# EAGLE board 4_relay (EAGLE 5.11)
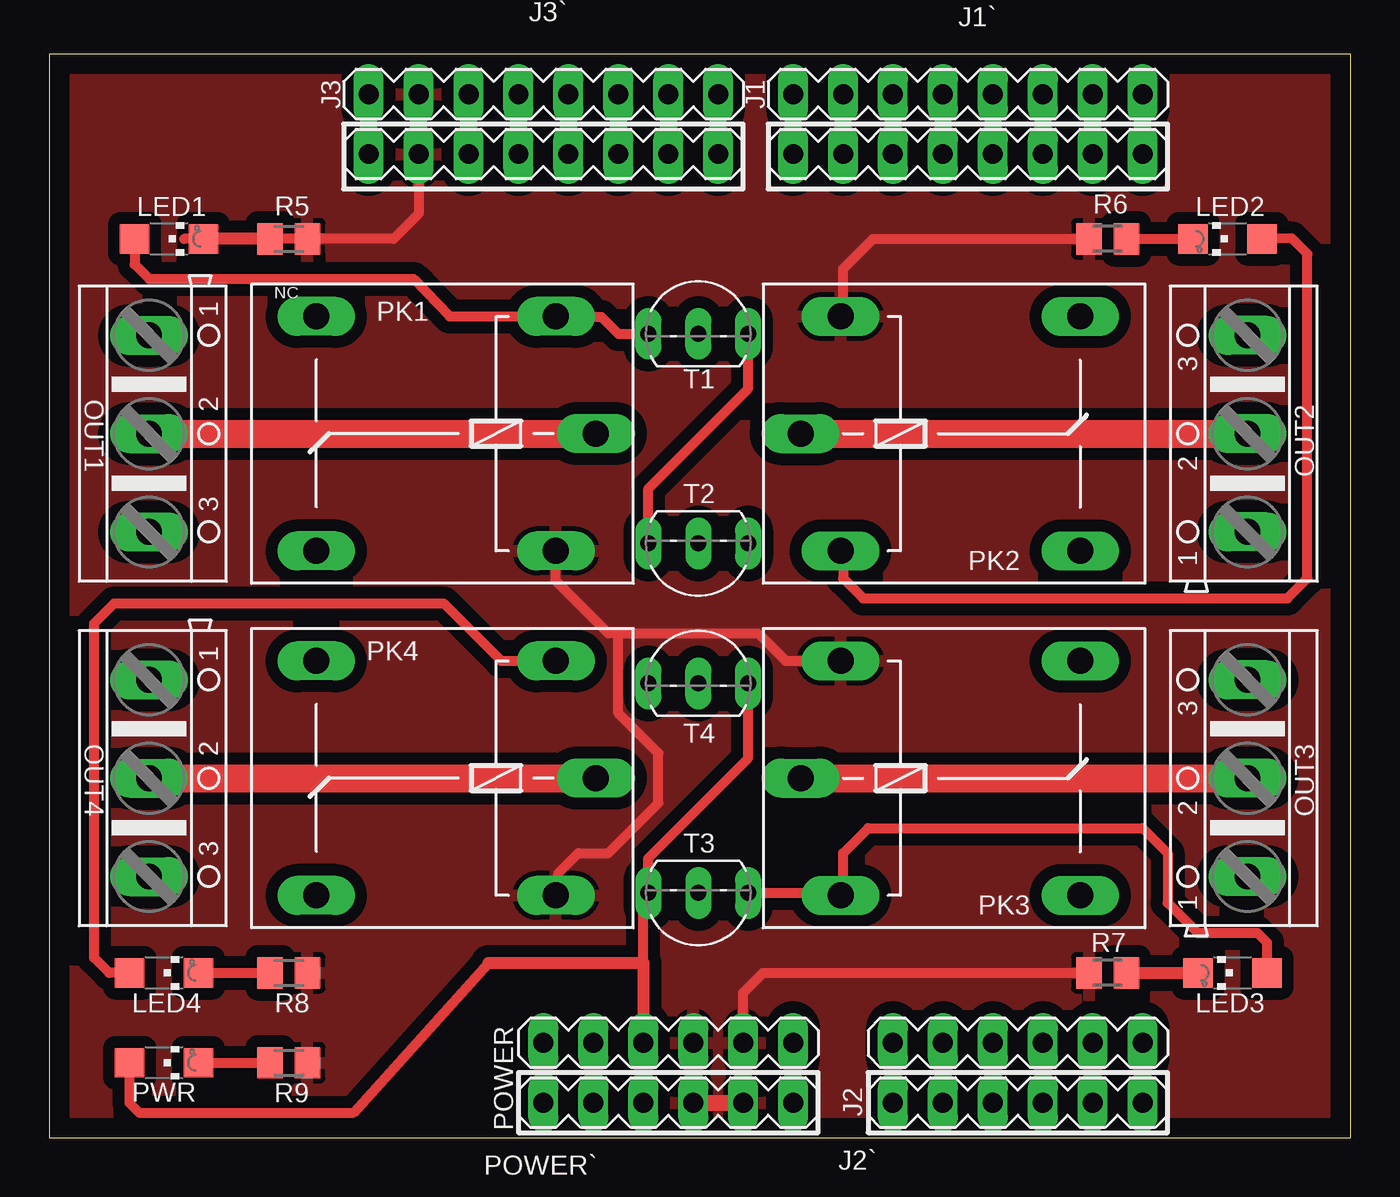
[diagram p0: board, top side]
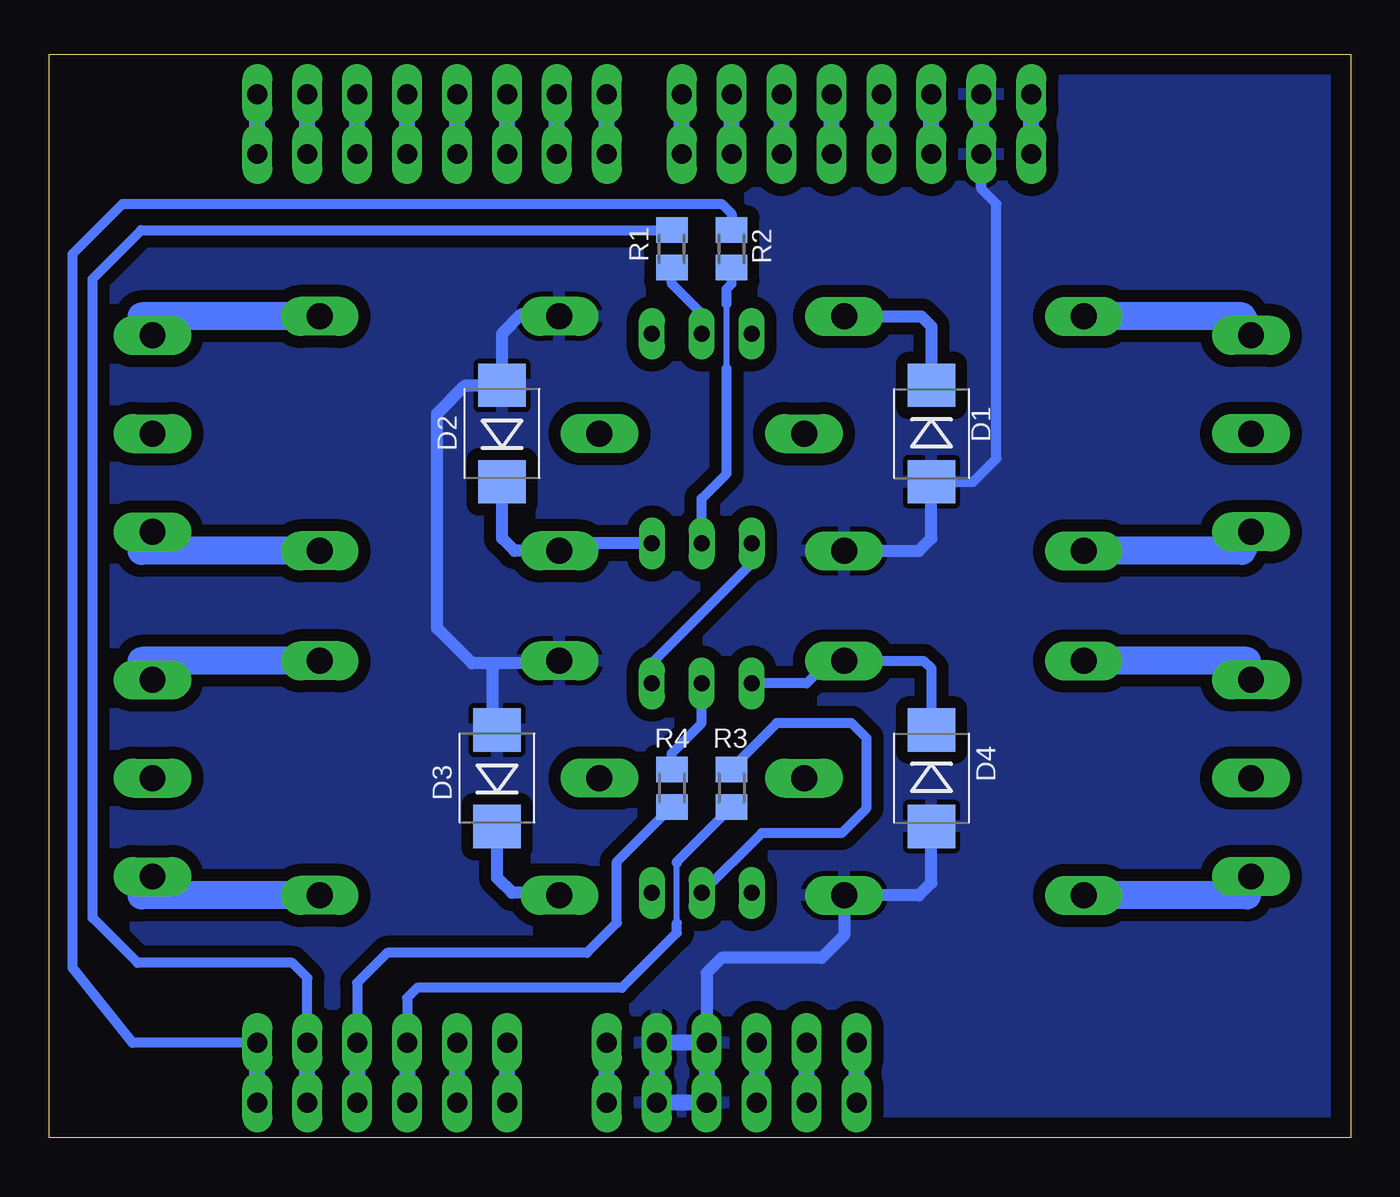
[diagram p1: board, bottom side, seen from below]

Size 66.22 x 55.11 mm. Coordinates in mm from the lower left corner, seen from the top.
Outline: 0,0 66.22,0 66.22,55.11 0,55.11 0,0
Copper layers (1*16): Top 0.035mm / dielectric 1.5mm / Bottom 0.035mm
Design rules "default": minimum track width 10mil, minimum drill 24mil, track to track 8mil, track to pad 8mil, pad to pad 8mil, via to via 8mil, smd to smd 8mil, copper to edge 40mil, drill to drill 8mil, minimum pad ring 10mil, minimum via ring 8mil, stop-mask expansion 4mil, vias tented up to drill 0mil, thermal gap 10mil

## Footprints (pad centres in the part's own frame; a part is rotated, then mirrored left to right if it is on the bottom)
DIODE-HV = smd 2.2 x 2.4: A 2.454,0; C -2.454,0
MA08-1 = drill 1.016 long: 1 -8.89,0; 2 -6.35,0; 3 -3.81,0; 4 -1.27,0; 5 1.27,0; 6 3.81,0; 7 6.35,0; 8 8.89,0
MA06-1 = drill 1.016 long: 1 -6.35,0; 2 -3.81,0; 3 -1.27,0; 4 1.27,0; 5 3.81,0; 6 6.35,0
CHIPLED_1206 = smd 1.5 x 1.5: A 0,-1.75; C 0,1.75
AK500/3 = drill 1.321 long: 1 -5.004,0; 2 0,0; 3 5.004,0
G5LE = drill 1.321 long: 1 -7.493,-5.969; 2 -7.493,5.969; O 4.699,5.969; P -9.525,0; S 4.699,-5.969
M0805 = smd 1.3 x 1.6: 1 -0.95,0; 2 0.95,0
TO92-EBC = drill 0.813 long: B 0,-1.27; C -2.54,-1.27; E 2.54,-1.27

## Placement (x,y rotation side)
D1  [DIODE-HV]  21.34,35.81 270 bottom
D2  [DIODE-HV]  43.18,35.81 90 bottom
D3  [DIODE-HV]  43.43,18.29 90 bottom
D4  [DIODE-HV]  21.34,18.29 270 bottom
J1  [MA08-1]  46.74,53.09 0 top
J1`  [MA08-1]  46.74,50.04 0 top
J2  [MA06-1]  49.28,4.83 0 top
J2`  [MA06-1]  49.28,1.78 0 top
J3  [MA08-1]  25.15,53.09 0 top
J3`  [MA08-1]  25.15,50.04 0 top
LED1  [CHIPLED_1206]  6.1,45.72 270 top
LED2  [CHIPLED_1206]  59.94,45.72 90 top
LED3  [CHIPLED_1206]  60.2,8.38 90 top
LED4  [CHIPLED_1206]  5.84,8.38 270 top
OUT1  [AK500/3]  5.08,35.81 270 top
OUT2  [AK500/3]  60.96,35.81 90 top
OUT3  [AK500/3]  60.96,18.29 90 top
OUT4  [AK500/3]  5.08,18.29 270 top
PK1  G5LE  [G5LE]  18.29,35.81 180 top
PK2  G5LE  [G5LE]  47.75,35.81 0 top
PK3  G5LE  [G5LE]  47.75,18.29 0 top
PK4  G5LE  [G5LE]  18.29,18.29 180 top
POWER  [MA06-1]  31.5,4.83 0 top
POWER`  [MA06-1]  31.5,1.78 0 top
PWR  [CHIPLED_1206]  5.84,3.81 270 top
R1  [M0805]  34.54,45.21 270 bottom
R2  [M0805]  31.5,45.21 270 bottom
R3  [M0805]  31.5,17.78 90 bottom
R4  [M0805]  34.54,17.78 90 bottom
R5  [M0805]  12.19,45.72 180 top
R6  [M0805]  53.85,45.72 0 top
R7  [M0805]  53.85,8.38 0 top
R8  [M0805]  12.19,8.38 180 top
R9  [M0805]  12.19,3.81 180 top
T1  BC558B  [TO92-EBC]  33.02,42.16 0 top
T2  BC558B  [TO92-EBC]  33.02,28.96 180 top
T3  BC558B  [TO92-EBC]  33.02,11.18 180 top
T4  BC558B  [TO92-EBC]  33.02,24.38 0 top

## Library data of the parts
D1-D4 = moja
J1 J1` J2 J2` J3 J3` POWER POWER` = con-lstb_v2; OC_FARNELL: unknown; OC_NEWARK: unknown
LED1-LED4 PWR = led
OUT1-OUT4 = con-ptr500; OC_FARNELL: unknown; OC_NEWARK: unknown
PK1-PK4 = relay2; OC_FARNELL: unknown; OC_NEWARK: unknown
R1-R9 = rcl
T1-T4 = transistor-pnp

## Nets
GND: D1.A D2.A D3.A D4.A J3.2 J3`.2 PK1.2 PK2.2 PK3.2 PK4.2 POWER.4 POWER.5 POWER`.4 POWER`.5 R5.1 R6.1 R7.1 R8.1 R9.1
N$1: OUT1.2 PK1.P
N$2: OUT1.3 PK1.O
N$3: OUT1.1 PK1.S
N$4: R1.2 T1.B
N$5: LED1.C R5.2
N$6: D1.C LED1.A PK1.1 T1.C
N$7: OUT3.2 PK3.P
N$8: POWER.1 POWER`.1
N$9: POWER.2 POWER`.2
N$10: OUT2.2 PK2.P
N$11: OUT2.3 PK2.O
N$12: OUT2.1 PK2.S
N$13: LED2.C R6.2
N$14: D2.C LED2.A PK2.1 T2.C
N$15: OUT3.3 PK3.O
N$16: R2.2 T2.B
N$17: POWER.6 POWER`.6
N$18: OUT3.1 PK3.S
N$19: LED3.C R7.2
N$20: D3.C LED3.A PK3.1 T3.C
N$21: R3.2 T3.B
N$22: J3.1 J3`.1
N$23: OUT4.2 PK4.P
N$24: OUT4.3 PK4.O
N$25: OUT4.1 PK4.S
N$26: LED4.C R8.2
N$27: D4.C LED4.A PK4.1 T4.C
N$28: R4.2 T4.B
N$29: PWR.C R9.2
N$30: J3.7 J3`.7
N$31: J3.8 J3`.8
N$32: J2.1 J2`.1
N$33: J2.2 J2`.2
N$38: J1.1 J1`.1
N$39: J1.2 J1`.2
N$40: J1.3 J1`.3
N$41: J1.4 J1`.4
N$42: J1.5 J1`.5
N$43: J1.6 J1`.6
N$44: J1.7 J1`.7
N$45: J1.8 J1`.8
PB2: J3.6 J3`.6
PB3: J3.5 J3`.5
PB4: J3.4 J3`.4
PB5: J3.3 J3`.3
PC2: J2.3 J2`.3 R3.1
PC3: J2.4 J2`.4 R4.1
PC4: J2.5 J2`.5 R1.1
PC5: J2.6 J2`.6 R2.1
VCC: POWER.3 POWER`.3 PWR.A T1.E T2.E T3.E T4.E

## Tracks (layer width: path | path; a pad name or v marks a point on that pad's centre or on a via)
GND
  Top 0.254: PK1.2 25.65,29.46
  Top 0.508: R7.1 36.32,8.38 35.31,7.37 POWER.5 | 6.86,45.72 R5.1 17.53,45.72 18.8,46.99 J3`.2 | R6.1 41.91,45.72 40.39,44.2 40.39,41.91 | PK3.2 37.47,24.26 36.07,25.65 28.96,25.65 | PK1.2 25.78,28.32 28.45,25.65 28.96,25.65 | 28.96,25.65 28.96,21.59 30.99,19.56 30.99,17.02 28.45,14.48 26.92,14.48 25.91,13.46 25.91,12.45
  Top 0.61: PK2.2 40.39,41.91 | PK1.2 25.65,29.97 | 25.65,12.45 PK4.2 25.91,12.45
  Top 0.813: POWER.4 POWER`.4 POWER`.5 POWER.5 | J3`.2 J3.2
  Bottom 0.254: 22.1,12.45 23.37,12.45 PK4.2 | 43.69,21.34 D3.A | PK3.2 41.15,23.88
  Bottom 0.508: D1.A 19.22,33.36 18.03,34.54 18.03,47.5 18.8,48.26 J3`.2
  Bottom 0.61: PK2.2 40.39,41.91 42.16,41.91 43.18,40.89 D2.A 45.04,38.27 46.48,36.83 46.48,25.91 44.7,24.13 43.43,24.13 | 43.43,24.13 40.39,24.13 PK3.2 | 43.69,21.34 43.69,23.88 43.43,24.13 | D1.A 21.34,30.48 21.97,29.85 PK1.2 | D4.A 21.34,12.95 21.97,12.32 PK4.2 25.78,10.29 26.92,9.14 32,9.14 32.77,8.38 POWER.4
  Bottom 0.813: J3`.2 J3.2 | POWER.4 POWER`.4 POWER`.5 POWER.5 POWER.4
  pour Bottom (isolate 0.61): -1.52,56.64 67.82,56.9 67.82,-1.27 -1.52,-1.52
  pour Top (isolate 0.61): -1.27,56.39 67.06,56.13 67.06,-0.76 -1.27,-0.51
N$1
  Top 1.422: OUT1.2 PK1.P
N$2
  Bottom 1.422: PK1.O 5.54,29.85 OUT1.3
N$3
  Bottom 1.422: PK1.S 5.54,41.78 OUT1.1
N$4
  Bottom 0.508: R1.2 34.54,43.43 33.02,41.91 T1.B
N$5
  Top 0.254: LED1.C R5.2
  Top 0.61: R5.2 7.62,45.72
N$6
  Top 0.508: T1.C 28.96,40.89 28.09,41.76 25.76,41.76 | LED1.A 4.35,44.42 5.08,43.69 18.54,43.69 20.37,41.78 PK1.1
  Top 0.61: PK1.1 25.76,41.76
  Bottom 0.61: D1.C 21.34,41.28 21.84,41.78 PK1.1
N$7
  Top 1.422: PK3.P OUT3.2
N$8
  Top 0.813: POWER`.1 POWER.1
  Bottom 0.813: POWER`.1 POWER.1
N$9
  Top 0.813: POWER`.2 POWER.2
  Bottom 0.813: POWER`.2 POWER.2
N$10
  Top 1.422: PK2.P OUT2.2
N$11
  Bottom 1.422: PK2.O 61.52,41.78 OUT2.3
N$12
  Bottom 1.422: PK2.S 61.52,29.85 OUT2.1
N$13
  Top 0.508: R6.2 LED2.C
N$14
  Top 0.508: LED2.A 63.22,45.75 64.01,44.96 64.01,28.45 62.99,27.43 41.4,27.43 40.39,28.45 40.39,29.72
  Top 0.61: PK2.1 40.39,29.72
  Bottom 0.61: T2.C 39.88,30.23 PK2.1 42.55,29.85 43.18,30.48 D2.C
N$15
  Bottom 1.422: PK3.O 61.52,24.26 OUT3.3
N$16
  Bottom 0.305: 31.75,39.12 31.75,42.42
  Bottom 0.508: R2.2 31.5,43.43 31.75,43.18 31.75,42.42 | 31.75,39.12 31.75,33.78 33.02,32.51 T2.B
N$17
  Top 0.813: POWER`.6 POWER.6
  Bottom 0.813: POWER`.6 POWER.6
N$18
  Bottom 1.422: PK3.S 61.52,12.32 OUT3.1
N$19
  Top 0.508: LED3.C 58.67,8.38
  Top 0.61: R7.2 LED3.C
N$20
  Top 0.508: T3.C 40.13,12.45 PK3.1 40.39,12.45 40.39,14.48 41.66,15.75 55.63,15.75 56.9,14.48 56.9,11.94 58.42,10.41 61.47,10.41 61.95,9.93 LED3.A
  Bottom 0.61: D3.C 43.43,13.21 42.67,12.45 40.39,12.45 PK3.1 40.13,12.45
N$21
  Bottom 0.508: R3.2 31.5,18.8 29.21,21.08 25.4,21.08 24.64,20.32 24.64,16.76 25.91,15.49 29.97,15.49 T3.B
N$22
  Top 0.813: J3`.1 J3.1
  Bottom 0.813: J3`.1 J3.1
N$23
  Top 1.422: OUT4.2 PK4.P
N$24
  Bottom 1.422: PK4.O 5.28,12.32 OUT4.3
N$25
  Bottom 1.422: PK4.S 5.28,24.26 OUT4.1
N$26
  Top 0.508: LED4.C R8.2
N$27
  Top 0.508: LED4.A 3.05,8.38 2.29,9.14 2.29,26.16 3.3,27.18 20.07,27.18 22.99,24.26 PK4.1
  Bottom 0.508: T4.C 27.69,23.11 26.54,24.26 PK4.1 21.74,24.26 21.34,23.88 D4.C
N$28
  Bottom 0.508: R4.2 34.54,19.56 33.02,21.08 T4.B
N$29
  Top 0.508: PWR.C R9.2
N$30
  Top 0.813: J3`.7 J3.7
  Bottom 0.813: J3`.7 J3.7
N$31
  Top 0.813: J3`.8 J3.8
  Bottom 0.813: J3`.8 J3.8
N$32
  Top 0.813: J2`.1 J2.1
  Bottom 0.813: J2`.1 J2.1
N$33
  Top 0.813: J2`.2 J2.2
  Bottom 0.813: J2`.2 J2.2
N$38
  Top 0.813: J1`.1 J1.1
  Bottom 0.813: J1`.1 J1.1
N$39
  Top 0.813: J1`.2 J1.2
  Bottom 0.813: J1`.2 J1.2
N$40
  Top 0.813: J1`.3 J1.3
  Bottom 0.813: J1`.3 J1.3
N$41
  Top 0.813: J1`.4 J1.4
  Bottom 0.813: J1`.4 J1.4
N$42
  Top 0.813: J1`.5 J1.5
  Bottom 0.813: J1`.5 J1.5
N$43
  Top 0.813: J1`.6 J1.6
  Bottom 0.813: J1`.6 J1.6
N$44
  Top 0.813: J1`.7 J1.7
  Bottom 0.813: J1`.7 J1.7
N$45
  Top 0.813: J1`.8 J1.8
  Bottom 0.813: J1`.8 J1.8
PB2
  Top 0.813: J3`.6 J3.6
  Bottom 0.813: J3`.6 J3.6
PB3
  Top 0.813: J3`.5 J3.5
  Bottom 0.813: J3`.5 J3.5
PB4
  Top 0.813: J3`.4 J3.4
  Bottom 0.813: J3`.4 J3.4
PB5
  Top 0.813: J3`.3 J3.3
  Bottom 0.813: J3`.3 J3.3
PC2
  Top 0.813: J2.3 J2`.3
  Bottom 0.305: 34.29,10.92 34.29,13.97
  Bottom 0.508: J2.3 48.01,7.11 47.5,7.62 37.08,7.62 34.29,10.41 34.29,10.92 | 34.29,13.97 34.29,14.04 R3.1
  Bottom 0.813: J2.3 J2`.3
PC3
  Top 0.813: J2.4 J2`.4
  Bottom 0.508: J2.4 50.55,7.87 49.02,9.4 38.86,9.4 37.34,10.92 37.34,14.04 R4.1
  Bottom 0.813: J2.4 J2`.4
PC4
  Top 0.813: J2`.5 J2.5
  Bottom 0.508: R1.1 61.53,46.16 64.01,43.69 64.01,11.18 61.72,8.89 53.85,8.89 53.09,8.13 J2.5
  Bottom 0.813: J2`.5 J2.5
PC5
  Top 0.813: J2`.6 J2.6
  Bottom 0.508: J2.6 61.98,4.83 65.02,8.64 65.02,44.96 62.48,47.5 32,47.5 31.5,46.99 R2.1
  Bottom 0.813: J2`.6 J2.6
VCC
  Top 0.508: T1.E 35.56,38.1 30.48,33.02 T2.E | T3.E 30.48,14.22 35.56,19.3 T4.E | PWR.A 4.09,1.75 4.57,1.27 15.49,1.27 22.35,8.89 | 30.23,8.89 30.23,11.94
  Top 0.61: POWER.3 30.23,8.89 22.35,8.89 | 30.23,11.94 30.48,12.19 T3.E
  Top 0.813: POWER.3 POWER`.3
  Bottom 0.508: T2.E 30.48,29.21 35.56,24.13 T4.E
  Bottom 0.813: POWER.3 POWER`.3

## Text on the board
tNames: NC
